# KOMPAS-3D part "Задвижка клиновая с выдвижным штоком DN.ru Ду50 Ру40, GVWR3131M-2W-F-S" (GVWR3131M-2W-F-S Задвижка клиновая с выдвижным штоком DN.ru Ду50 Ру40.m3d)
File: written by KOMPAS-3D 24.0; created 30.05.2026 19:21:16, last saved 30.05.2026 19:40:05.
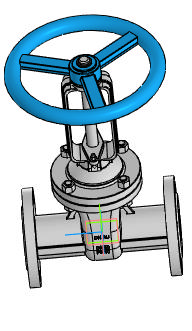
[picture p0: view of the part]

Document properties: Автор: R2D2; Полное имя файла: E:\Работа\Зайцев\GVWR3131M-2W-F-S Задвижка клиновая с выдвижным штоком DN.ru Ду50-100 Ру40\исходные материалы\DN50\DN50\GVWR3131M-2W-F-S Задвижка клиновая с выдвижным штоком DN.ru Ду50 Ру40.m3d

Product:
- Part/product: Задвижка клиновая с выдвижным штоком DN.ru Ду50 Ру40  | designation GVWR3131M-2W-F-S
    Масса: 12
    Раздел спецификации: Прочие изделия
    Примечание: D040-08605

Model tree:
1. Операция без истории:1

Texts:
  GVWR3131M-2W-F-S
